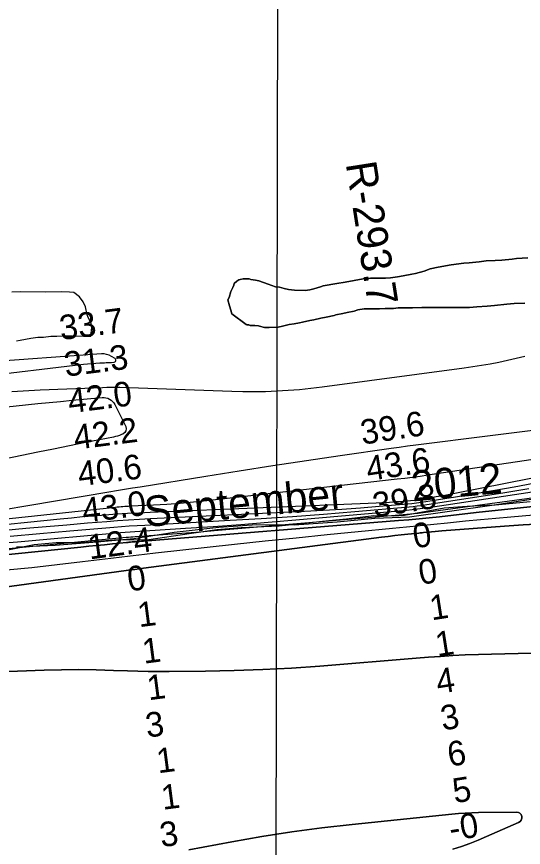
# Model space of a CAD drawing. Extents: x 3192986 to 3230865, y 867483 to 892886.
# Drawn here: x 3201724 to 3203100, y 879588 to 881843 of the extents above; entities that cross this region are included whole.
import ezdxf

# ---------------------------------------------------------------- set-up
doc = ezdxf.new("R2010")
doc.units = 0
for name, color, linetype in [('V-GRID-MAJR', 7, 'Continuous'), ('V-RIVR-EDGE', 7, 'Continuous'), ('V-RIVR-IDEN', 7, 'Continuous'), ('V-RIVR-RANG', 7, 'Continuous'), ('V-RIVR-RANG-IDEN', 7, 'Continuous'), ('V-SITE-VEGE', 7, 'Continuous'), ('V-TOPO-DPTH', 7, 'Continuous'), ('V-TOPO-MAJR', 7, 'Continuous'), ('V-TOPO-MINR', 7, 'Continuous'), ('V-TOPO-WATR', 7, 'Continuous')]:
    doc.layers.add(name, color=color, linetype=linetype)

msp = doc.modelspace()

# ---------------------------------------------------------------- linework, layer by layer
at = {"layer": 'V-GRID-MAJR'}
msp.add_spline([(3202414.6, 872911), (3202427.8, 878971.7), (3202441, 885034.4), (3202454.2, 891097.1), (3202454.2, 891099)], degree=3, dxfattribs=at)
at = {"layer": 'V-RIVR-EDGE'}
msp.add_lwpolyline([(3203128.2, 880532.8), (3203021.2, 880517), (3202947.3, 880513.7), (3202885.2, 880508.6), (3202777.7, 880488.9), (3202748.6, 880486.8), (3202694.7, 880487.8), (3202619.9, 880478.8), (3202572.1, 880474.2), (3202436.9, 880460.2), (3202334.3, 880455.2), (3202268.2, 880449.7), (3202192.5, 880438.6), (3202083, 880422.8), (3201988.2, 880422.1), (3201901.3, 880415), (3201831.3, 880414.3), (3201772.1, 880408.8), (3201677.3, 880389.9)], dxfattribs=at)
at = {"layer": 'V-SITE-VEGE'}
for p, q in [((3203112.6, 881188.3), (3203081.5, 881186.5)), ((3202904.3, 881169.3), (3202869.4, 881162.8)), ((3202938.3, 881173.8), (3202904.3, 881169.3)), ((3202953.3, 881174.7), (3202938.3, 881173.8)), ((3202980.7, 881177.5), (3202953.3, 881174.7)), ((3202999.5, 881180.2), (3202980.7, 881177.5)), ((3203024, 881181.1), (3202999.5, 881180.2)), ((3203041.9, 881181.9), (3203024, 881181.1)), ((3203070.2, 881184.7), (3203041.9, 881181.9)), ((3203081.5, 881186.5), (3203070.2, 881184.7)), ((3202797.8, 881144.2), (3202774.2, 881139.6)), ((3202807.2, 881146.1), (3202797.8, 881144.2)), ((3202830.8, 881152.6), (3202807.2, 881146.1)), ((3202846.8, 881158.2), (3202830.8, 881152.6)), ((3202869.4, 881162.8), (3202846.8, 881158.2)), ((3202321.9, 881125.3), (3202315.3, 881118.7)), ((3202327.6, 881129.1), (3202321.9, 881125.3)), ((3202331.3, 881130), (3202327.6, 881129.1)), ((3202339.8, 881131.8), (3202331.3, 881130)), ((3202355.8, 881131.8), (3202339.8, 881131.8)), ((3202360.5, 881129.9), (3202355.8, 881131.8)), ((3202372.8, 881128), (3202360.5, 881129.9)), ((3202382.2, 881126), (3202372.8, 881128)), ((3202407.6, 881116.5), (3202382.2, 881126)), ((3202616.8, 881122.3), (3202594.2, 881118.6)), ((3202664.9, 881131.5), (3202616.8, 881122.3)), ((3202685.6, 881133.4), (3202664.9, 881131.5)), ((3202726.1, 881133.2), (3202685.6, 881133.4)), ((3202739.3, 881134.1), (3202726.1, 881133.2)), ((3202758.2, 881136.8), (3202739.3, 881134.1)), ((3202774.2, 881139.6), (3202758.2, 881136.8)), ((3202311.5, 881107.5), (3202305.8, 881097.1)), ((3202314.3, 881114), (3202311.5, 881107.5)), ((3202315.3, 881118.7), (3202314.3, 881114)), ((3202417, 881113.7), (3202407.6, 881116.5)), ((3202427.4, 881109.8), (3202417, 881113.7)), ((3202437.7, 881108.9), (3202427.4, 881109.8)), ((3202450.9, 881105), (3202437.7, 881108.9)), ((3202462.2, 881102.2), (3202450.9, 881105)), ((3202479.1, 881100.2), (3202462.2, 881102.2)), ((3202507.4, 881100.1), (3202479.1, 881100.2)), ((3202520.6, 881102), (3202507.4, 881100.1)), ((3202531, 881104.7), (3202520.6, 881102)), ((3202549.8, 881109.4), (3202531, 881104.7)), ((3202556.5, 881112.2), (3202549.8, 881109.4)), ((3202594.2, 881118.6), (3202556.5, 881112.2)), ((3201736, 881095.7), (3201711.5, 881094.9)), ((3201801.9, 881095.5), (3201736, 881095.7)), ((3201845.3, 881096.2), (3201801.9, 881095.5)), ((3201867.9, 881095.2), (3201845.3, 881096.2)), ((3201879.2, 881094.2), (3201867.9, 881095.2)), ((3201895.2, 881082.9), (3201879.2, 881094.2)), ((3201904.5, 881068.7), (3201895.2, 881082.9)), ((3202301, 881081.1), (3202298.2, 881074.5)), ((3202305.8, 881097.1), (3202301, 881081.1)), ((3201911.1, 881055.5), (3201904.5, 881068.7)), ((3201915.7, 881033.8), (3201911.1, 881055.5)), ((3202298.2, 881074.5), (3202301.9, 881058.5)), ((3202301.9, 881058.5), (3202305.6, 881046.2)), ((3202747.5, 881051.2), (3202760.7, 881053)), ((3202760.7, 881053), (3202799.3, 881052.8)), ((3202799.3, 881052.8), (3202824.7, 881053.7)), ((3202824.7, 881053.7), (3202953.8, 881053.2)), ((3202953.8, 881053.2), (3202973.6, 881055)), ((3202973.6, 881055), (3203001.9, 881056.8)), ((3203001.9, 881056.8), (3203021.7, 881058.6)), ((3203021.7, 881058.6), (3203055.6, 881062.2)), ((3203055.6, 881062.2), (3203075.4, 881064)), ((3203075.4, 881064), (3203104.6, 881065.8)), ((3201919.4, 881024.4), (3201915.7, 881033.8)), ((3202305.6, 881046.2), (3202308.4, 881036.8)), ((3202308.4, 881036.8), (3202347.8, 881007.5)), ((3202564.6, 881027.4), (3202586.3, 881032)), ((3202586.3, 881032), (3202591, 881033.8)), ((3202591, 881033.8), (3202609.9, 881037.5)), ((3202609.9, 881037.5), (3202622.1, 881040.3)), ((3202622.1, 881040.3), (3202641, 881044)), ((3202641, 881044), (3202650.4, 881046.8)), ((3202650.4, 881046.8), (3202668.3, 881049.6)), ((3202668.3, 881049.6), (3202684.3, 881050.4)), ((3202684.3, 881050.4), (3202709.8, 881050.4)), ((3202709.8, 881050.4), (3202724.9, 881051.2)), ((3202724.9, 881051.2), (3202747.5, 881051.2)), ((3201926.9, 881011.1), (3201919.4, 881024.4)), ((3201928.8, 880998.9), (3201926.9, 881011.1)), ((3202347.8, 881007.5), (3202349.7, 881006.5)), ((3202464.7, 881007), (3202477.9, 881008.8)), ((3202477.9, 881008.8), (3202492, 881011.6)), ((3202492, 881011.6), (3202500.5, 881013.5)), ((3202500.5, 881013.5), (3202520.3, 881018.1)), ((3202520.3, 881018.1), (3202531.6, 881019.9)), ((3202531.6, 881019.9), (3202550.5, 881024.6)), ((3202550.5, 881024.6), (3202564.6, 881027.4)), ((3201925.9, 880975.3), (3201928.8, 880998.9)), ((3202349.7, 881006.5), (3202354.4, 881006.5)), ((3202354.4, 881006.5), (3202358.2, 881004.6)), ((3202358.2, 881004.6), (3202371.4, 881004.5)), ((3202371.4, 881004.5), (3202380.8, 881003.6)), ((3202380.8, 881003.6), (3202383.6, 881002.6)), ((3202383.6, 881002.6), (3202397.7, 880999.7)), ((3202397.7, 880999.7), (3202410, 880999.7)), ((3202410, 880999.7), (3202434.5, 881000.5)), ((3202434.5, 881000.5), (3202445.8, 881003.3)), ((3202445.8, 881003.3), (3202464.7, 881007)), ((3201724.2, 880962.9), (3201733.6, 880964.8)), ((3201733.6, 880964.8), (3201748.7, 880967.5)), ((3201748.7, 880967.5), (3201762.8, 880970.3)), ((3201762.8, 880970.3), (3201781.7, 880973.1)), ((3201781.7, 880973.1), (3201796.8, 880973)), ((3201796.8, 880973), (3201817.5, 880975.7)), ((3201817.5, 880975.7), (3201833.5, 880975.7)), ((3201833.5, 880975.7), (3201856.1, 880976.5)), ((3201856.1, 880976.5), (3201875, 880976.5)), ((3201875, 880976.5), (3201906.1, 880975.4)), ((3201906.1, 880975.4), (3201925.9, 880975.3)), ((3203014.6, 880516), (3202899.9, 880500.1)), ((3203119, 880525.7), (3203014.6, 880516)), ((3202899.9, 880500.1), (3202790.8, 880484.1)), ((3202594.3, 880470.9), (3202478.2, 880462.7)), ((3202697.3, 880480.6), (3202594.3, 880470.9)), ((3202790.8, 880484.1), (3202697.3, 880480.6)), ((3202273.2, 880456.5), (3202152.4, 880442.9)), ((3202376.9, 880463.1), (3202273.2, 880456.5)), ((3202478.2, 880462.7), (3202376.9, 880463.1)), ((3202042.4, 880425.4), (3201942.7, 880416.5)), ((3202152.4, 880442.9), (3202042.4, 880425.4)), ((3201828.9, 880407.5), (3201723.6, 880402.5)), ((3201942.7, 880416.5), (3201828.9, 880407.5))]:
    msp.add_line(p, q, dxfattribs=at)
for points in [[(3202358.2, 881004.6), (3202354.4, 881006.5), (3202349.7, 881006.5), (3202347.8, 881007.5), (3202308.4, 881036.8), (3202305.6, 881046.2), (3202301.9, 881058.5), (3202298.2, 881074.5), (3202301, 881081.1), (3202305.8, 881097.1), (3202311.5, 881107.5), (3202314.3, 881114), (3202315.3, 881118.7), (3202321.9, 881125.3), (3202327.6, 881129.1), (3202331.3, 881130), (3202339.8, 881131.8), (3202355.8, 881131.8), (3202360.5, 881129.9), (3202372.8, 881128), (3202382.2, 881126), (3202407.6, 881116.5), (3202417, 881113.7), (3202427.4, 881109.8), (3202437.7, 881108.9), (3202450.9, 881105), (3202462.2, 881102.2), (3202479.1, 881100.2), (3202507.4, 881100.1), (3202520.6, 881102), (3202531, 881104.7), (3202549.8, 881109.4), (3202556.5, 881112.2), (3202594.2, 881118.6), (3202616.8, 881122.3), (3202664.9, 881131.5), (3202685.6, 881133.4), (3202726.1, 881133.2), (3202739.3, 881134.1), (3202758.2, 881136.8), (3202774.2, 881139.6), (3202797.8, 881144.2), (3202807.2, 881146.1), (3202830.8, 881152.6), (3202846.8, 881158.2), (3202869.4, 881162.8), (3202904.3, 881169.3), (3202938.3, 881173.8), (3202953.3, 881174.7), (3202980.7, 881177.5), (3202999.5, 881180.2), (3203024, 881181.1), (3203041.9, 881181.9), (3203070.2, 881184.7), (3203081.5, 881186.5), (3203112.6, 881188.3)], [(3203104.6, 881065.8), (3203075.4, 881064), (3203055.6, 881062.2), (3203021.7, 881058.6), (3203001.9, 881056.8), (3202973.6, 881055), (3202953.8, 881053.2), (3202824.7, 881053.7), (3202799.3, 881052.8), (3202760.7, 881053), (3202747.5, 881051.2), (3202724.9, 881051.2), (3202709.8, 881050.4), (3202684.3, 881050.4), (3202668.3, 881049.6), (3202650.4, 881046.8), (3202641, 881044), (3202622.1, 881040.3), (3202609.9, 881037.5), (3202591, 881033.8), (3202586.3, 881032), (3202564.6, 881027.4), (3202550.5, 881024.6), (3202531.6, 881019.9), (3202520.3, 881018.1), (3202500.5, 881013.5), (3202492, 881011.6), (3202477.9, 881008.8), (3202464.7, 881007), (3202445.8, 881003.3), (3202434.5, 881000.5), (3202410, 880999.7), (3202397.7, 880999.7), (3202383.6, 881002.6), (3202380.8, 881003.6), (3202371.4, 881004.5), (3202358.2, 881004.6)]]:
    msp.add_lwpolyline(points, dxfattribs=at)
at = {"layer": 'V-TOPO-DPTH'}
for points in [[(3203327.7, 880583), (3202842.4, 880509.8), (3202827.6, 880507.7), (3202812.9, 880505.8), (3202798, 880504.1), (3202783.2, 880502.7), (3202482.8, 880476.2), (3202407.7, 880469.8), (3202332.7, 880463.9), (3202257.6, 880458.5), (3202182.5, 880453.5), (3202058.5, 880445.8), (3202045.4, 880444.9), (3202032.2, 880444), (3202019.1, 880442.9), (3202006, 880441.8), (3201726.7, 880416.8), (3201667.7, 880411.5)], [(3201434.1, 880356.2), (3201898.6, 880403.1), (3201920, 880405.3), (3201941.4, 880407.4), (3201962.8, 880409.5), (3201984.3, 880411.6), (3202022.8, 880415.3), (3202027.1, 880415.8), (3202029.3, 880416), (3202033.6, 880416.5), (3202038, 880416.9), (3202040.1, 880417.1), (3202046.7, 880417.7), (3202052.1, 880418.1), (3202057.6, 880418.5), (3202063, 880419), (3202068.5, 880419.4), (3202761, 880474.8), (3202789, 880477.2), (3202817, 880479.7), (3202844.9, 880482.6), (3202872.8, 880485.6), (3202971.9, 880496.8), (3203049.4, 880505.3), (3203127, 880513.6)], [(3201434.1, 880356.2), (3201898.6, 880403.1), (3201920, 880405.3), (3201941.4, 880407.4), (3201962.8, 880409.5), (3201984.3, 880411.6), (3202022.8, 880415.3), (3202027.1, 880415.8), (3202029.3, 880416), (3202033.6, 880416.5), (3202038, 880416.9), (3202040.1, 880417.1), (3202046.7, 880417.7), (3202052.1, 880418.1), (3202057.6, 880418.5), (3202063, 880419), (3202068.5, 880419.4), (3202761, 880474.8), (3202789, 880477.2), (3202817, 880479.7), (3202844.9, 880482.6), (3202872.8, 880485.6), (3202971.9, 880496.8), (3203049.4, 880505.3), (3203127, 880513.6)], [(3201485.4, 880266.4), (3202021.9, 880339.3), (3202033.7, 880340.9), (3202045.4, 880342.4), (3202057.2, 880344), (3202069, 880345.5), (3202715, 880429.6), (3202733, 880431.9), (3202750.9, 880434.1), (3202768.9, 880436.1), (3202786.9, 880438.1), (3202816.9, 880441.2), (3202819.9, 880441.6), (3202822.9, 880441.9), (3202825.9, 880442.1), (3202828.8, 880442.4), (3202841.7, 880443.7), (3202851.1, 880444.5), (3202860.5, 880445.4), (3202869.9, 880446.1), (3202879.3, 880446.9), (3203049.4, 880459.9), (3203099.4, 880463.2), (3203469, 880482.2)], [(3203469, 880482.2), (3203099.4, 880463.2), (3203049.4, 880459.9), (3202879.3, 880446.9), (3202869.9, 880446.1), (3202860.5, 880445.4), (3202851.1, 880444.5), (3202841.7, 880443.7), (3202828.8, 880442.4), (3202825.9, 880442.1), (3202822.9, 880441.9), (3202819.9, 880441.6), (3202816.9, 880441.2), (3202786.9, 880438.1), (3202768.9, 880436.1), (3202750.9, 880434.1), (3202733, 880431.9), (3202715, 880429.6), (3202069, 880345.5), (3202057.2, 880344), (3202045.4, 880342.4), (3202033.7, 880340.9), (3202021.9, 880339.3), (3201485.4, 880266.4)], [(3203480.8, 880123.9), (3202942.1, 880110.8), (3202908.9, 880108.6), (3202875.6, 880106.4), (3202842.3, 880103.9), (3202809.1, 880101.3), (3202547.8, 880080.1), (3202470.3, 880074.6), (3202392.6, 880070.3), (3202314.9, 880067.6), (3202237.2, 880066), (3202138.1, 880065), (3202109.8, 880065), (3202081.6, 880065.2), (3202053.4, 880065.8), (3202025.1, 880066.8), (3201987.3, 880068.3), (3201940.1, 880069.6), (3201893, 880070.3), (3201845.8, 880069.8), (3201798.7, 880068.6), (3201557.2, 880059.7)], [(3203480.8, 880123.9), (3202942.1, 880110.8), (3202908.9, 880108.6), (3202875.6, 880106.4), (3202842.3, 880103.9), (3202809.1, 880101.3), (3202547.8, 880080.1), (3202470.3, 880074.6), (3202392.6, 880070.3), (3202314.9, 880067.6), (3202237.2, 880066), (3202138.1, 880065), (3202109.8, 880065), (3202081.6, 880065.2), (3202053.4, 880065.8), (3202025.1, 880066.8), (3201987.3, 880068.3), (3201940.1, 880069.6), (3201893, 880070.3), (3201845.8, 880069.8), (3201798.7, 880068.6), (3201557.2, 880059.7)], [(3202191.9, 879580.9), (3202308.2, 879602.8), (3202389.7, 879617), (3202471.3, 879629.9), (3202553.3, 879640.8), (3202635.5, 879650.2), (3202906, 879678), (3202924.2, 879679.7), (3202942.4, 879681), (3202960.6, 879681.8), (3202978.9, 879682.3), (3203081.7, 879683.6), (3203086.8, 879682.5), (3203091, 879680.4), (3203094, 879676.7), (3203096.2, 879671.9), (3203096.1, 879666.6), (3203094.8, 879662), (3203091.7, 879658.3), (3203087.5, 879655.2), (3203000.5, 879617), (3202977.9, 879607.5), (3202955.2, 879598.6), (3202932.1, 879590.4), (3202908.9, 879582.8)], [(3202191.9, 879580.9), (3202308.2, 879602.8), (3202389.7, 879617), (3202471.3, 879629.9), (3202553.3, 879640.8), (3202635.5, 879650.2), (3202906, 879678), (3202924.2, 879679.7), (3202942.4, 879681), (3202960.6, 879681.8), (3202978.9, 879682.3), (3203081.7, 879683.6), (3203086.8, 879682.5), (3203091, 879680.4), (3203094, 879676.7), (3203096.2, 879671.9), (3203096.1, 879666.6), (3203094.8, 879662), (3203091.7, 879658.3), (3203087.5, 879655.2), (3203000.5, 879617), (3202977.9, 879607.5), (3202955.2, 879598.6), (3202932.1, 879590.4), (3202908.9, 879582.8)]]:
    msp.add_lwpolyline(points, dxfattribs=at)
at = {"layer": 'V-TOPO-MAJR'}
for points in [[(3201711.1, 880825.4), (3201788.6, 880829.6), (3201957.8, 880836.8), (3201969.4, 880837.1), (3201981, 880837.3), (3201992.7, 880837.2), (3202004.3, 880837), (3202308.2, 880826.3), (3202338.9, 880825.6), (3202369.7, 880825.4), (3202400.4, 880825.9), (3202431.2, 880827), (3202461.9, 880828.8), (3202492.5, 880831.2), (3202523.1, 880834.4), (3202553.6, 880838.1), (3202939.5, 880889.9), (3202963.3, 880893.3), (3202986.9, 880897), (3203010.6, 880901), (3203034.1, 880905.3), (3203057.6, 880910.2), (3203080.9, 880915.6), (3203104.1, 880921.8)], [(3203382.4, 880641.2), (3202918.6, 880549.1), (3202900.4, 880545.6), (3202882.2, 880542.2), (3202863.9, 880539.1), (3202845.6, 880536), (3202813.7, 880530.8), (3202811.4, 880530.5), (3202806.6, 880529.9), (3202804.3, 880529.7), (3202773, 880527), (3202755, 880525.6), (3202736.9, 880524.4), (3202718.9, 880523.3), (3202700.9, 880522.5), (3202086.9, 880497.1), (3202056.3, 880495.6), (3202025.7, 880494), (3201995.1, 880492), (3201964.5, 880489.9), (3201934, 880487.4), (3201903.4, 880484.8), (3201872.9, 880482), (3201842.4, 880479), (3201380, 880431.9)]]:
    msp.add_lwpolyline(points, dxfattribs=at)
at = {"layer": 'V-TOPO-MINR'}
for points in [[(3201994, 880909.1), (3201993.5, 880911.8), (3201991.6, 880914.9), (3201982, 880920.8), (3201975.4, 880924.1), (3201968.7, 880926.4), (3201961.6, 880927.5), (3201954.3, 880927.7), (3201630.8, 880904.1)], [(3201330.7, 880830.8), (3201905.5, 880899.5), (3201916.6, 880900.7), (3201927.8, 880901.8), (3201938.9, 880902.5), (3201950.1, 880903.1), (3201962.5, 880903.7), (3201967.5, 880903.9), (3201972.4, 880904.1), (3201977.4, 880904.4), (3201982.3, 880904.7), (3201989.1, 880905.1), (3201992.3, 880906.9), (3201994, 880909.1)], [(3201361, 880748), (3201782.1, 880792.5), (3201812.9, 880795.6), (3201843.7, 880798.7), (3201874.6, 880801.7), (3201905.4, 880804.5), (3201956.3, 880809.2), (3201961.6, 880809.2), (3201966.7, 880808.6), (3201971.7, 880807.1), (3201976.5, 880805), (3201980.9, 880802.1), (3201984.8, 880798.8), (3201988, 880794.8), (3201990.7, 880790.3), (3202020.4, 880730.3), (3202021.6, 880724.1), (3202021.1, 880718.5), (3202017.9, 880714), (3202012.9, 880710), (3202009.3, 880708.5), (3202003.8, 880706.4), (3201998.3, 880704.5), (3201992.6, 880702.9), (3201986.9, 880701.6), (3201911.6, 880686.6), (3201868.2, 880677.9), (3201824.8, 880669.2), (3201781.4, 880660.4), (3201738, 880651.5), (3201379, 880577.9)], [(3201469.4, 880467.9), (3201974.5, 880552.9), (3201995.8, 880556.5), (3202017.2, 880560), (3202038.5, 880563.5), (3202059.8, 880567), (3202237.6, 880595.8), (3202328.8, 880610.3), (3202420.1, 880624.5), (3202511.5, 880638.3), (3202602.9, 880651.6), (3202741.3, 880671.5), (3202763.5, 880674.7), (3202785.8, 880677.7), (3202808.1, 880680.7), (3202830.4, 880683.5), (3202988.5, 880703.2), (3203060.9, 880712.2), (3203133.4, 880721.2)], [(3203297, 880665.8), (3202840.9, 880598.1), (3202820.1, 880595.1), (3202799.2, 880592.3), (3202778.4, 880589.7), (3202757.5, 880587.2), (3202240.4, 880528.6), (3202204.3, 880524.9), (3202168.2, 880521.6), (3202132, 880519), (3202095.8, 880516.9), (3202033.5, 880513.9), (3202028.4, 880513.6), (3202023.2, 880513.3), (3202018.1, 880513), (3202013, 880512.6), (3202007.9, 880512.2), (3202002.8, 880511.8), (3201997.7, 880511.3), (3201992.6, 880510.8), (3201365.8, 880443.4)], [(3203327.7, 880583), (3202842.4, 880509.8), (3202827.6, 880507.7), (3202812.9, 880505.8), (3202798, 880504.1), (3202783.2, 880502.7), (3202482.8, 880476.2), (3202407.7, 880469.8), (3202332.7, 880463.9), (3202257.6, 880458.5), (3202182.5, 880453.5), (3202058.5, 880445.8), (3202045.4, 880444.9), (3202032.2, 880444), (3202019.1, 880442.9), (3202006, 880441.8), (3201726.7, 880416.8), (3201667.7, 880411.5)], [(3203128.1, 880575.8), (3203075.3, 880565.9), (3203022.4, 880556.4), (3202969.5, 880547.4), (3202916.4, 880538.7), (3202823.3, 880523.9), (3202816.8, 880522.9), (3202810.3, 880522), (3202803.8, 880521.3), (3202797.3, 880520.7), (3202709, 880513.1), (3202658.4, 880509.1), (3202607.7, 880505.4), (3202557, 880502.3), (3202506.2, 880499.6), (3202087, 880479.4), (3202057.5, 880477.9), (3202028, 880476.1), (3201998.6, 880474.1), (3201969.1, 880471.9), (3201916.3, 880467.7), (3201860.5, 880463), (3201804.6, 880458.2), (3201748.8, 880453.1), (3201693.1, 880447.9)], [(3203115.2, 880561), (3203049.6, 880550.5), (3202832.8, 880516.8), (3202822.2, 880515.3), (3202811.6, 880513.9), (3202800.9, 880512.7), (3202790.2, 880511.7), (3202642.4, 880498.8), (3202557.8, 880491.9), (3202473.2, 880485.5), (3202388.4, 880479.9), (3202303.7, 880474.8), (3202072.2, 880462.1), (3202051.2, 880460.8), (3202030.2, 880459.5), (3202009.2, 880457.9), (3201988.3, 880456.2), (3201868.3, 880446.1), (3201787.3, 880439.1), (3201706.4, 880432)], [(3203230.4, 880550), (3202855.4, 880499.6), (3202835, 880497), (3202814.6, 880494.6), (3202794.2, 880492.5), (3202773.7, 880490.6), (3202261, 880447.1), (3202223.2, 880444), (3202185.4, 880440.9), (3202147.6, 880438.1), (3202109.7, 880435.3), (3202046.1, 880430.9), (3202040.1, 880430.4), (3202034.1, 880429.9), (3202028.1, 880429.4), (3202022, 880428.9), (3201580, 880386.7)], [(3203434.4, 880516.7), (3203066.5, 880484.6), (3203025.4, 880480.9), (3202984.3, 880477.1), (3202943.2, 880473.1), (3202902.1, 880469), (3202894.6, 880468.2), (3202857.3, 880464.4), (3202819.9, 880460.7), (3202782.6, 880457), (3202745.2, 880453.4), (3202651.7, 880444.4), (3202567.7, 880436.1), (3202483.6, 880427.7), (3202399.6, 880418.8), (3202315.6, 880409.8), (3202101.5, 880386.3), (3202071.1, 880382.9), (3202040.6, 880379.4), (3202010.2, 880375.8), (3201979.8, 880372.1), (3201903.2, 880362.7), (3201834.5, 880354.6), (3201765.7, 880347.1), (3201696.8, 880340.4)], [(3203469, 880482.2), (3203099.4, 880463.2), (3203049.4, 880459.9), (3202879.3, 880446.9), (3202869.9, 880446.1), (3202860.5, 880445.4), (3202851.1, 880444.5), (3202841.7, 880443.7), (3202828.8, 880442.4), (3202825.9, 880442.1), (3202822.9, 880441.9), (3202819.9, 880441.6), (3202816.9, 880441.2), (3202786.9, 880438.1), (3202768.9, 880436.1), (3202750.9, 880434.1), (3202733, 880431.9), (3202715, 880429.6), (3202069, 880345.5), (3202057.2, 880344), (3202045.4, 880342.4), (3202033.7, 880340.9), (3202021.9, 880339.3), (3201485.4, 880266.4)], [(3201557.2, 880059.7), (3201798.7, 880068.6), (3201845.8, 880069.8), (3201893, 880070.3), (3201940.1, 880069.6), (3201987.3, 880068.3), (3202025.1, 880066.8), (3202053.4, 880065.8), (3202081.6, 880065.2), (3202109.8, 880065), (3202138.1, 880065), (3202237.2, 880066), (3202314.9, 880067.6), (3202392.6, 880070.3), (3202470.3, 880074.6), (3202547.8, 880080.1), (3202809.1, 880101.3), (3202842.3, 880103.9), (3202875.6, 880106.4), (3202908.9, 880108.6), (3202942.1, 880110.8), (3203480.8, 880123.9)], [(3202908.9, 879582.8), (3202932.1, 879590.4), (3202955.2, 879598.6), (3202977.9, 879607.5), (3203000.5, 879617), (3203087.5, 879655.2), (3203091.7, 879658.3), (3203094.8, 879662), (3203096.1, 879666.6), (3203096.2, 879671.9), (3203094, 879676.7), (3203091, 879680.4), (3203086.8, 879682.5), (3203081.7, 879683.6), (3202978.9, 879682.3), (3202960.6, 879681.8), (3202942.4, 879681), (3202924.2, 879679.7), (3202906, 879678), (3202635.5, 879650.2), (3202553.3, 879640.8), (3202471.3, 879629.9), (3202389.7, 879617), (3202308.2, 879602.8), (3202191.9, 879580.9)]]:
    msp.add_lwpolyline(points, dxfattribs=at)
at = {"layer": 'V-TOPO-WATR'}
msp.add_lwpolyline([(3203127, 880513.6), (3203049.4, 880505.3), (3202971.9, 880496.8), (3202872.8, 880485.6), (3202844.9, 880482.6), (3202817, 880479.7), (3202789, 880477.2), (3202761, 880474.8), (3202068.5, 880419.4), (3202063, 880419), (3202057.6, 880418.5), (3202052.1, 880418.1), (3202046.7, 880417.7), (3202040.1, 880417.1), (3202038, 880416.9), (3202033.6, 880416.5), (3202029.3, 880416), (3202027.1, 880415.8), (3202022.8, 880415.3), (3201984.3, 880411.6), (3201962.8, 880409.5), (3201941.4, 880407.4), (3201920, 880405.3), (3201898.6, 880403.1), (3201434.1, 880356.2)], dxfattribs=at)

# ---------------------------------------------------------------- texts
at = {"layer": 'V-RIVR-IDEN'}
msp.add_text('Waters     Edge      Aerial     Photos             September      2012', height=83, rotation=5.4766, dxfattribs=at).set_placement((3199950.4, 880253.6))
at = {"layer": 'V-RIVR-RANG'}
for s, rotation, p in [('33.7', 7.2683, (3201844.8, 880964.8)), ('31.3', 7.2683, (3201857.6, 880865.6)), ('42.0', 7.2683, (3201867.7, 880766.1)), ('39.6', 8.7883, (3202663.2, 880680.8)), ('42.2', 7.2683, (3201883.4, 880667.3)), ('43.6', 8.7883, (3202678.7, 880582)), ('40.6', 7.2683, (3201894.5, 880567.9)), ('43.0', 7.2683, (3201906.3, 880468.6)), ('39.8', 8.7883, (3202696.1, 880483.5)), ('0', 8.9337, (3202805.6, 880399.2)), ('12.4', 7.4478, (3201922.3, 880369.4)), ('0', 7.4478, (3202029.3, 880282.6)), ('0', 8.9337, (3202821.1, 880300.4)), ('1', 8.9337, (3202851.2, 880203.9)), ('1', 7.4478, (3202056.9, 880185.3)), ('1', 8.9337, (3202866.7, 880105.1)), ('1', 7.4478, (3202069.7, 880086.2)), ('4', 8.9337, (3202868.7, 880004.2)), ('1', 7.4478, (3202082.6, 879987)), ('3', 8.9337, (3202880.9, 879904.9)), ('3', 7.4478, (3202078.5, 879885.6)), ('6', 8.9337, (3202899.5, 879806.6)), ('1', 7.4478, (3202108.4, 879788.7)), ('5', 8.9337, (3202913.5, 879707.5)), ('1', 7.4478, (3202121.3, 879689.5)), ('-0', 8.9337, (3202903.7, 879604.8)), ('3', 7.4478, (3202117.2, 879588.1))]:
    msp.add_text(s, height=67, rotation=rotation, dxfattribs=at).set_placement(p)
at = {"layer": 'V-RIVR-RANG-IDEN'}
msp.add_text('R-293.7', height=83, rotation=278.9333, dxfattribs=at).set_placement((3202617.8, 881444.3))

doc.saveas('drawing.dxf')
